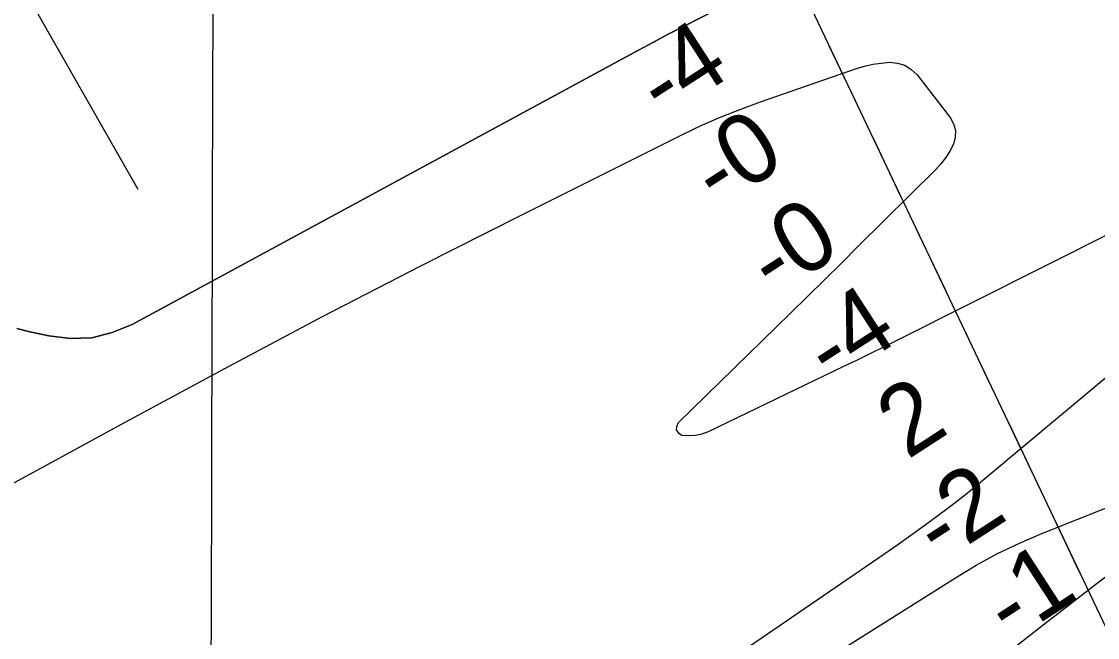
# Model space of a CAD drawing. Extents: x 3177385 to 3215275, y 903885 to 929304.
# Drawn here: x 3186650 to 3187679, y 911249 to 911838 of the extents above; entities that cross this region are included whole.
import ezdxf

# ---------------------------------------------------------------- set-up
doc = ezdxf.new("R2010")
doc.units = 0
for name, color, linetype in [('V-GRID-MAJR', 7, 'Continuous'), ('V-RIVR-FERY', 7, 'Continuous'), ('V-RIVR-RANG', 7, 'Continuous'), ('V-TOPO-DPTH', 7, 'Continuous'), ('V-TOPO-MINR', 7, 'Continuous')]:
    doc.layers.add(name, color=color, linetype=linetype)

msp = doc.modelspace()

# ---------------------------------------------------------------- linework, layer by layer
at = {"layer": 'V-GRID-MAJR'}
msp.add_spline([(3186826.1, 909324.9), (3186842, 915385.9), (3186857.8, 921448.8), (3186873.7, 927511.8), (3186873.7, 927513.7)], degree=3, dxfattribs=at)
at = {"layer": 'V-RIVR-FERY'}
for points in [[(3188606, 909326.5), (3186725.5, 913280.2)], [(3187447.5, 911762.3), (3187422.4, 911815)], [(3187490.4, 911672.1), (3187465.3, 911724.8)], [(3187533.3, 911581.9), (3187508.2, 911634.6)], [(3187576.2, 911491.7), (3187551.2, 911544.3)], [(3187619.1, 911401.5), (3187594.1, 911454.1)], [(3187662, 911311.3), (3187637, 911363.9)]]:
    msp.add_lwpolyline(points, dxfattribs=at)
at = {"layer": 'V-RIVR-RANG'}
msp.add_line((3186236.8, 912599.1), (3186760.9, 911677.7), dxfattribs=at)
at = {"layer": 'V-TOPO-DPTH'}
msp.add_lwpolyline([(3187726.8, 912004.6), (3187673, 911991.4), (3187641.2, 911983.1), (3187609.5, 911974.3), (3187578.1, 911964.7), (3187546.8, 911954.6), (3187515.9, 911943.4), (3187485.4, 911931.4), (3187455.3, 911918.2), (3187425.6, 911904.2), (3187298.6, 911841.2), (3187283.8, 911833.7), (3187269, 911826.2), (3187254.4, 911818.5), (3187239.8, 911810.7), (3186755.7, 911548.3), (3186736.4, 911540.5), (3186716.8, 911535.5), (3186696.5, 911534.9), (3186675.8, 911537.2), (3186656.3, 911541.6), (3186645.1, 911544.3)], dxfattribs=at)
msp.add_lwpolyline([(3187726.8, 912004.6), (3187673, 911991.4), (3187641.2, 911983.1), (3187609.5, 911974.3), (3187578.1, 911964.7), (3187546.8, 911954.6), (3187515.9, 911943.4), (3187485.4, 911931.4), (3187455.3, 911918.2), (3187425.6, 911904.2), (3187298.6, 911841.2), (3187283.8, 911833.7), (3187269, 911826.2), (3187254.4, 911818.5), (3187239.8, 911810.7), (3186755.7, 911548.3), (3186736.4, 911540.5), (3186716.8, 911535.5), (3186696.5, 911534.9), (3186675.8, 911537.2), (3186656.3, 911541.6), (3186645.1, 911544.3)], dxfattribs=at)
at = {"layer": 'V-TOPO-MINR'}
for points in [[(3186645.1, 911544.3), (3186656.3, 911541.6), (3186675.8, 911537.2), (3186696.5, 911534.9), (3186716.8, 911535.5), (3186736.4, 911540.5), (3186755.7, 911548.3), (3187239.8, 911810.7), (3187254.4, 911818.5), (3187269, 911826.2), (3187283.8, 911833.7), (3187298.6, 911841.2), (3187425.6, 911904.2), (3187455.3, 911918.2), (3187485.4, 911931.4), (3187515.9, 911943.4), (3187546.8, 911954.6), (3187578.1, 911964.7), (3187609.5, 911974.3), (3187641.2, 911983.1), (3187673, 911991.4), (3187726.8, 912004.6)], [(3186381.8, 911254.8), (3186749.4, 911455.2), (3186843.4, 911505.8), (3186937.6, 911555.7), (3187032.4, 911604.6), (3187127.6, 911652.8), (3187282.2, 911730.1), (3187300.4, 911738.8), (3187318.9, 911747), (3187337.7, 911754.4), (3187356.7, 911761.4), (3187448.5, 911793.1), (3187456.2, 911795.4), (3187464.1, 911797.2), (3187472.1, 911798.4), (3187480.2, 911799.1), (3187487.8, 911798.3), (3187494.8, 911796.3), (3187500.9, 911792.3), (3187506.5, 911787), (3187538.2, 911746.2), (3187541.4, 911740.2), (3187543.3, 911733.9), (3187542.9, 911727.4), (3187541.2, 911720.8), (3187537.7, 911714.2), (3187533.9, 911707.9), (3187529.3, 911702.1), (3187524.3, 911696.6), (3187450.2, 911623), (3187434.1, 911607), (3187417.8, 911591), (3187401.6, 911575), (3187385.3, 911559.1), (3187277.9, 911454), (3187276.3, 911450.3), (3187276.1, 911447), (3187278.1, 911444.5), (3187281.5, 911442.3), (3187288.1, 911441.9), (3187294.5, 911442.2), (3187300.8, 911443.7), (3187307, 911445.9), (3187436.5, 911508.2), (3187449.4, 911514.5), (3187462.3, 911520.8), (3187475.2, 911527.1), (3187488, 911533.5), (3187907.7, 911744.4)], [(3187887.9, 911664.8), (3187573.3, 911402), (3187561.5, 911392.3), (3187549.5, 911382.7), (3187537.5, 911373.4), (3187525.2, 911364.2), (3187512.9, 911355.2), (3187500.5, 911346.2), (3187488, 911337.4), (3187475.5, 911328.7), (3186654.6, 910766.3)], [(3186870.2, 910882.2), (3187543.1, 911305.9), (3187563.1, 911317.8), (3187583.4, 911328.9), (3187604.4, 911338.8), (3187625.7, 911348.1), (3187763.6, 911403.2)], [(3187805.8, 911397), (3187677.5, 911299.4), (3187652.2, 911280), (3187627, 911260.5), (3187601.9, 911240.8), (3187577, 911220.9), (3187335, 911027.2), (3187329.9, 911021), (3187326.6, 911014.3), (3187326.2, 911006.9), (3187327.6, 910999), (3187332, 910993.3), (3187337.2, 910989.7), (3187343.5, 910989.2), (3187350.5, 910990.6), (3187639.4, 911142.4), (3187662.8, 911154.7), (3187686.2, 911166.8)]]:
    msp.add_lwpolyline(points, dxfattribs=at)

# ---------------------------------------------------------------- texts
at = {"layer": 'V-RIVR-RANG'}
for s, p in [('-4', (3187263.7, 911743.7)), ('-0', (3187316.2, 911658.6)), ('-0', (3187369.7, 911574.1)), ('-4', (3187424.1, 911490.1)), ('2', (3187497.2, 911418.4)), ('-2', (3187528.5, 911319.5)), ('-1', (3187596, 911244.1))]:
    msp.add_text(s, height=67, rotation=32.9578, dxfattribs=at).set_placement(p)

doc.saveas('drawing.dxf')
